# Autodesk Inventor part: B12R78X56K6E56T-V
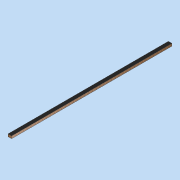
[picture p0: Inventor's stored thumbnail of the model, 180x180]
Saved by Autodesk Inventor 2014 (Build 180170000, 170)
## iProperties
Created: 2011-08
Part Number: B12R78X56K6E56T-V
Document SubType Name: Modeling
Designer: david.appleford
Density: 0.44944 g/cm^3
Description: Roof Edge Beam 3w - 6 Locks Ext 56mm + 68mm
Mass: 8000 g
Surface Area: 10689.3 cm^2
Volume: 17799.9 cm^3
Cost Center: £40.00
Material: 000 Redwood
Appearance: Wood (Oak)
Justset: False
Title: Roof Edge Beam 3w - 6 Locks
Author: david.appleford
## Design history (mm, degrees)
sketch "Sketch1"
  geometry: L1 (39, -34)-(-39, -34); L2 (-39, -34)-(-39, 3750); L3 (-39, 3750)-(39, 3750); L4 (39, 3750)-(39, -34); 1 further point
  constraints: 8 end point, 2 parallel, 1 horizontal, 1 perpendicular, 1 other
  dimensions: "d2" = 78 distance between parallel lines of L2 L4; "d3" = 34 distance from line of point (0, 0) L1; "d4" = 39 distance from line of point (0, 0) L2 (= 0.5 x d2); "d5" = 3784 distance of L3.end L1.start
extrude "Extrusion1" new body sketch "Sketch1" distance "d0" = 56; taper "d1" = 0 deg
feature "Move Face1" dims "d6" = 6
body "Solid1"
